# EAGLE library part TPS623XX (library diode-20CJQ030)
Ti's TPS623** 500-mA, 3-MHz SYNCHRONOUS STEP-DOWN CONVERTER Description: The TPS623xx device is a high-frequency synchronous step-down dc-dc converter optimized for battery-powered portable applications. Intended for low-power applications, the TPS623xx supports up to 500-mA load current and allows the use of tiny, low cost chip inductor and capacitors. The device is ideal for mobile phones and similar portable applications powered by a single-cell Li-Ion battery or by 3-cell NiMH/NiCd batteries. With an output voltage range from 5.4 V down to 0.6 V, the device supports low-voltage DSPs and processors in smart-phones, PDAs as well as notebooks, and handheld computers. The TPS62300 operates at 3-MHz fixed switching frequency and enters the power-save mode operation at light load currents to maintain high efficiency over the entire load current range. For low noise applications, the device can be forced into fixed frequency PWM mode by pulling the MODE/SYNC pin high. The device can also be synchronized to an external clock signal in the range of 3 MHz. In the shutdown mode, the current consumption is reduced to less than 1 uA. The TPS623xx is available in a 10-pin leadless package (3 ´ 3 mm QFN) and an 8-pin chip-scale package (CSP). Features: Up to 93% Efficiency at 3-MHz Operation Up to 500-mA Output Current at VI = 2.7 V 3-MHz Fixed Frequency Operation Best in Class Load and Line Transient Complete 1-mm Component Profile Solution -0.5% / +1.3% PWM DC Voltage Accuracy Over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
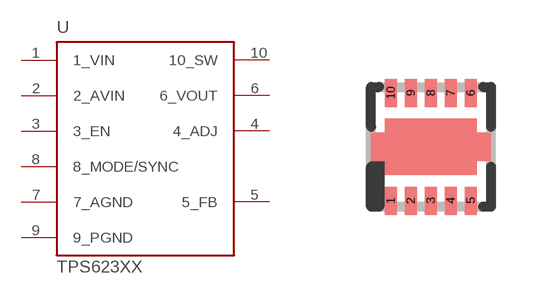
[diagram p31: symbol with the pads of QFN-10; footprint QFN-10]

Designator prefix U

## TPS623XX  [QFN-10]
1  1_VIN  pwr
2  2_AVIN  pwr
3  3_EN  pas
4  4_ADJ  pas
5  5_FB  pas
6  6_VOUT  pwr
7  7_AGND  pwr
8  8_MODE/SYNC  pas
9  9_PGND  pwr
10  10_SW  pwr

## Footprint QFN-10 (pad centres in mm)
TI TPS623xx 500mA, 3-MHz synchronous step-down converter in chip scale package (central pad is ground)
smd 0.3 x 0.7: 1 -1,-1.35; 2 -0.5,-1.35; 3 0,-1.35; 4 0.5,-1.35; 5 1,-1.35; 6 1,1.35; 7 0.5,1.35; 8 0,1.35; 9 -0.5,1.35; 10 -1,1.35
